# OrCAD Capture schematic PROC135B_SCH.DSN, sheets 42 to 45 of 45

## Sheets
42 42. OSCILLATOR: size C; title: SOC RESETs AND IOs, AND EXTERNAL LVCMOS CLOCK (OSCILLATOR)
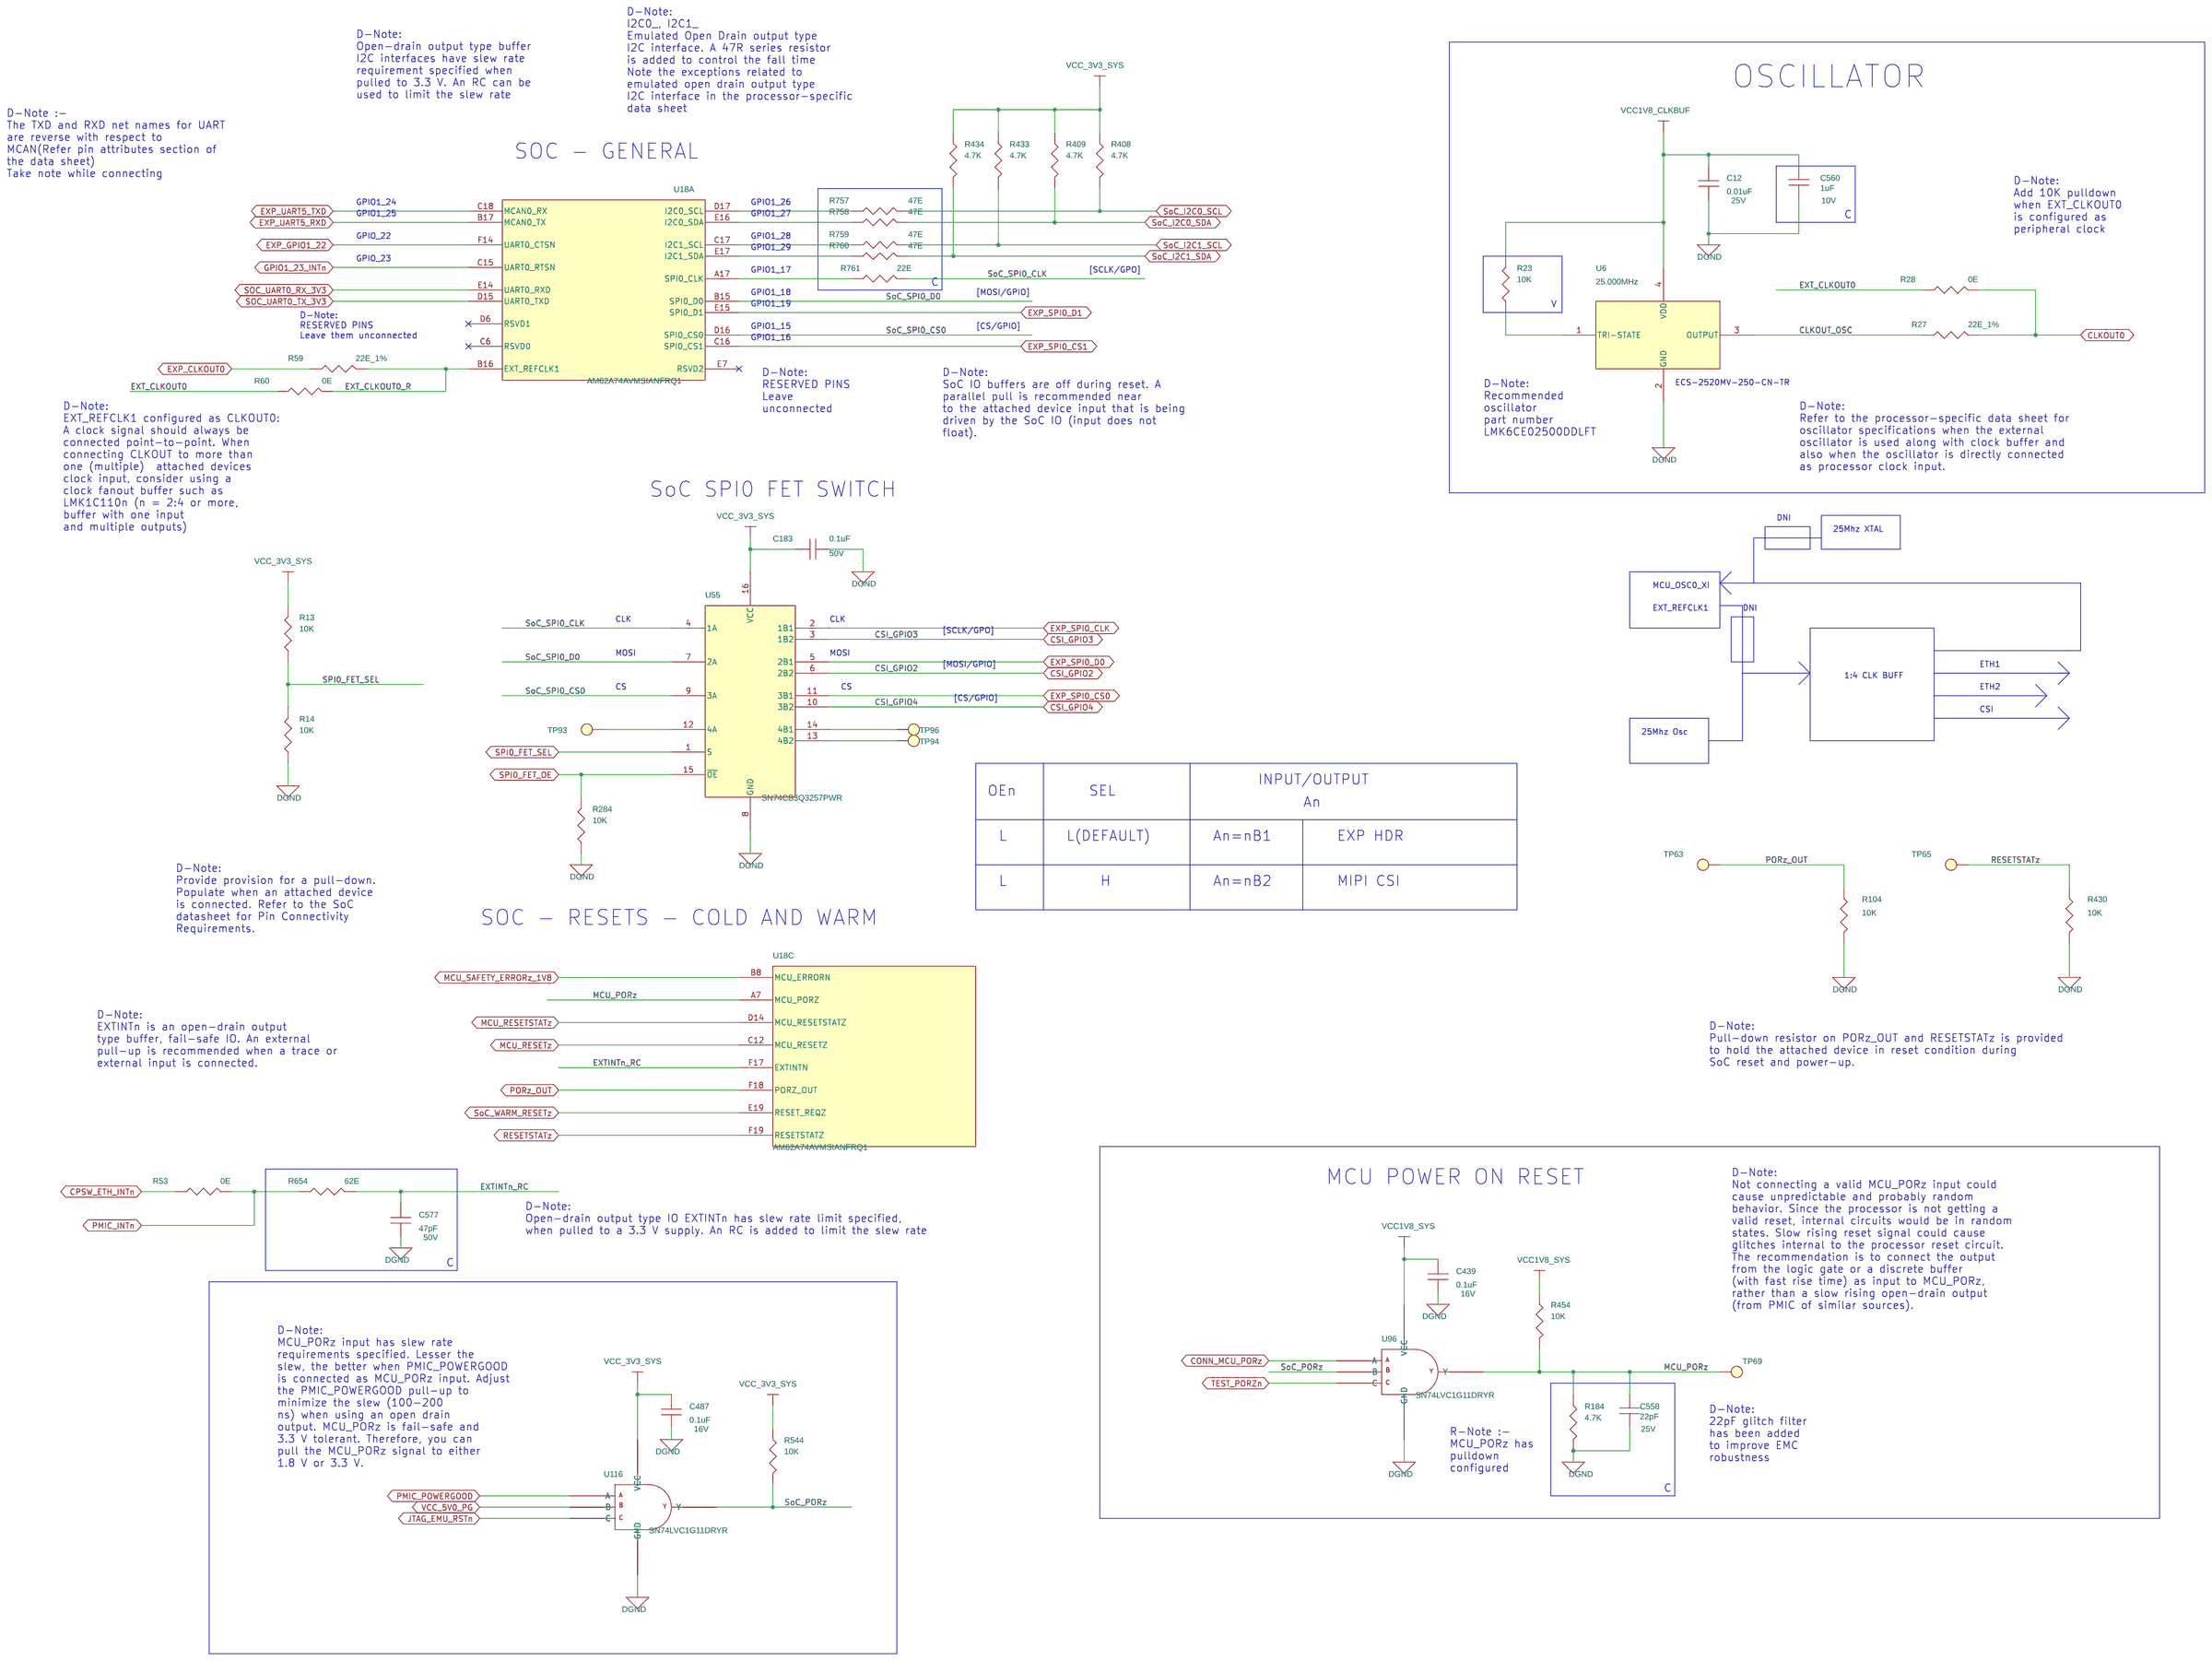
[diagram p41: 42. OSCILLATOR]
43 43. RESET: size C; title: SOC RESETS - COLD AND WARM
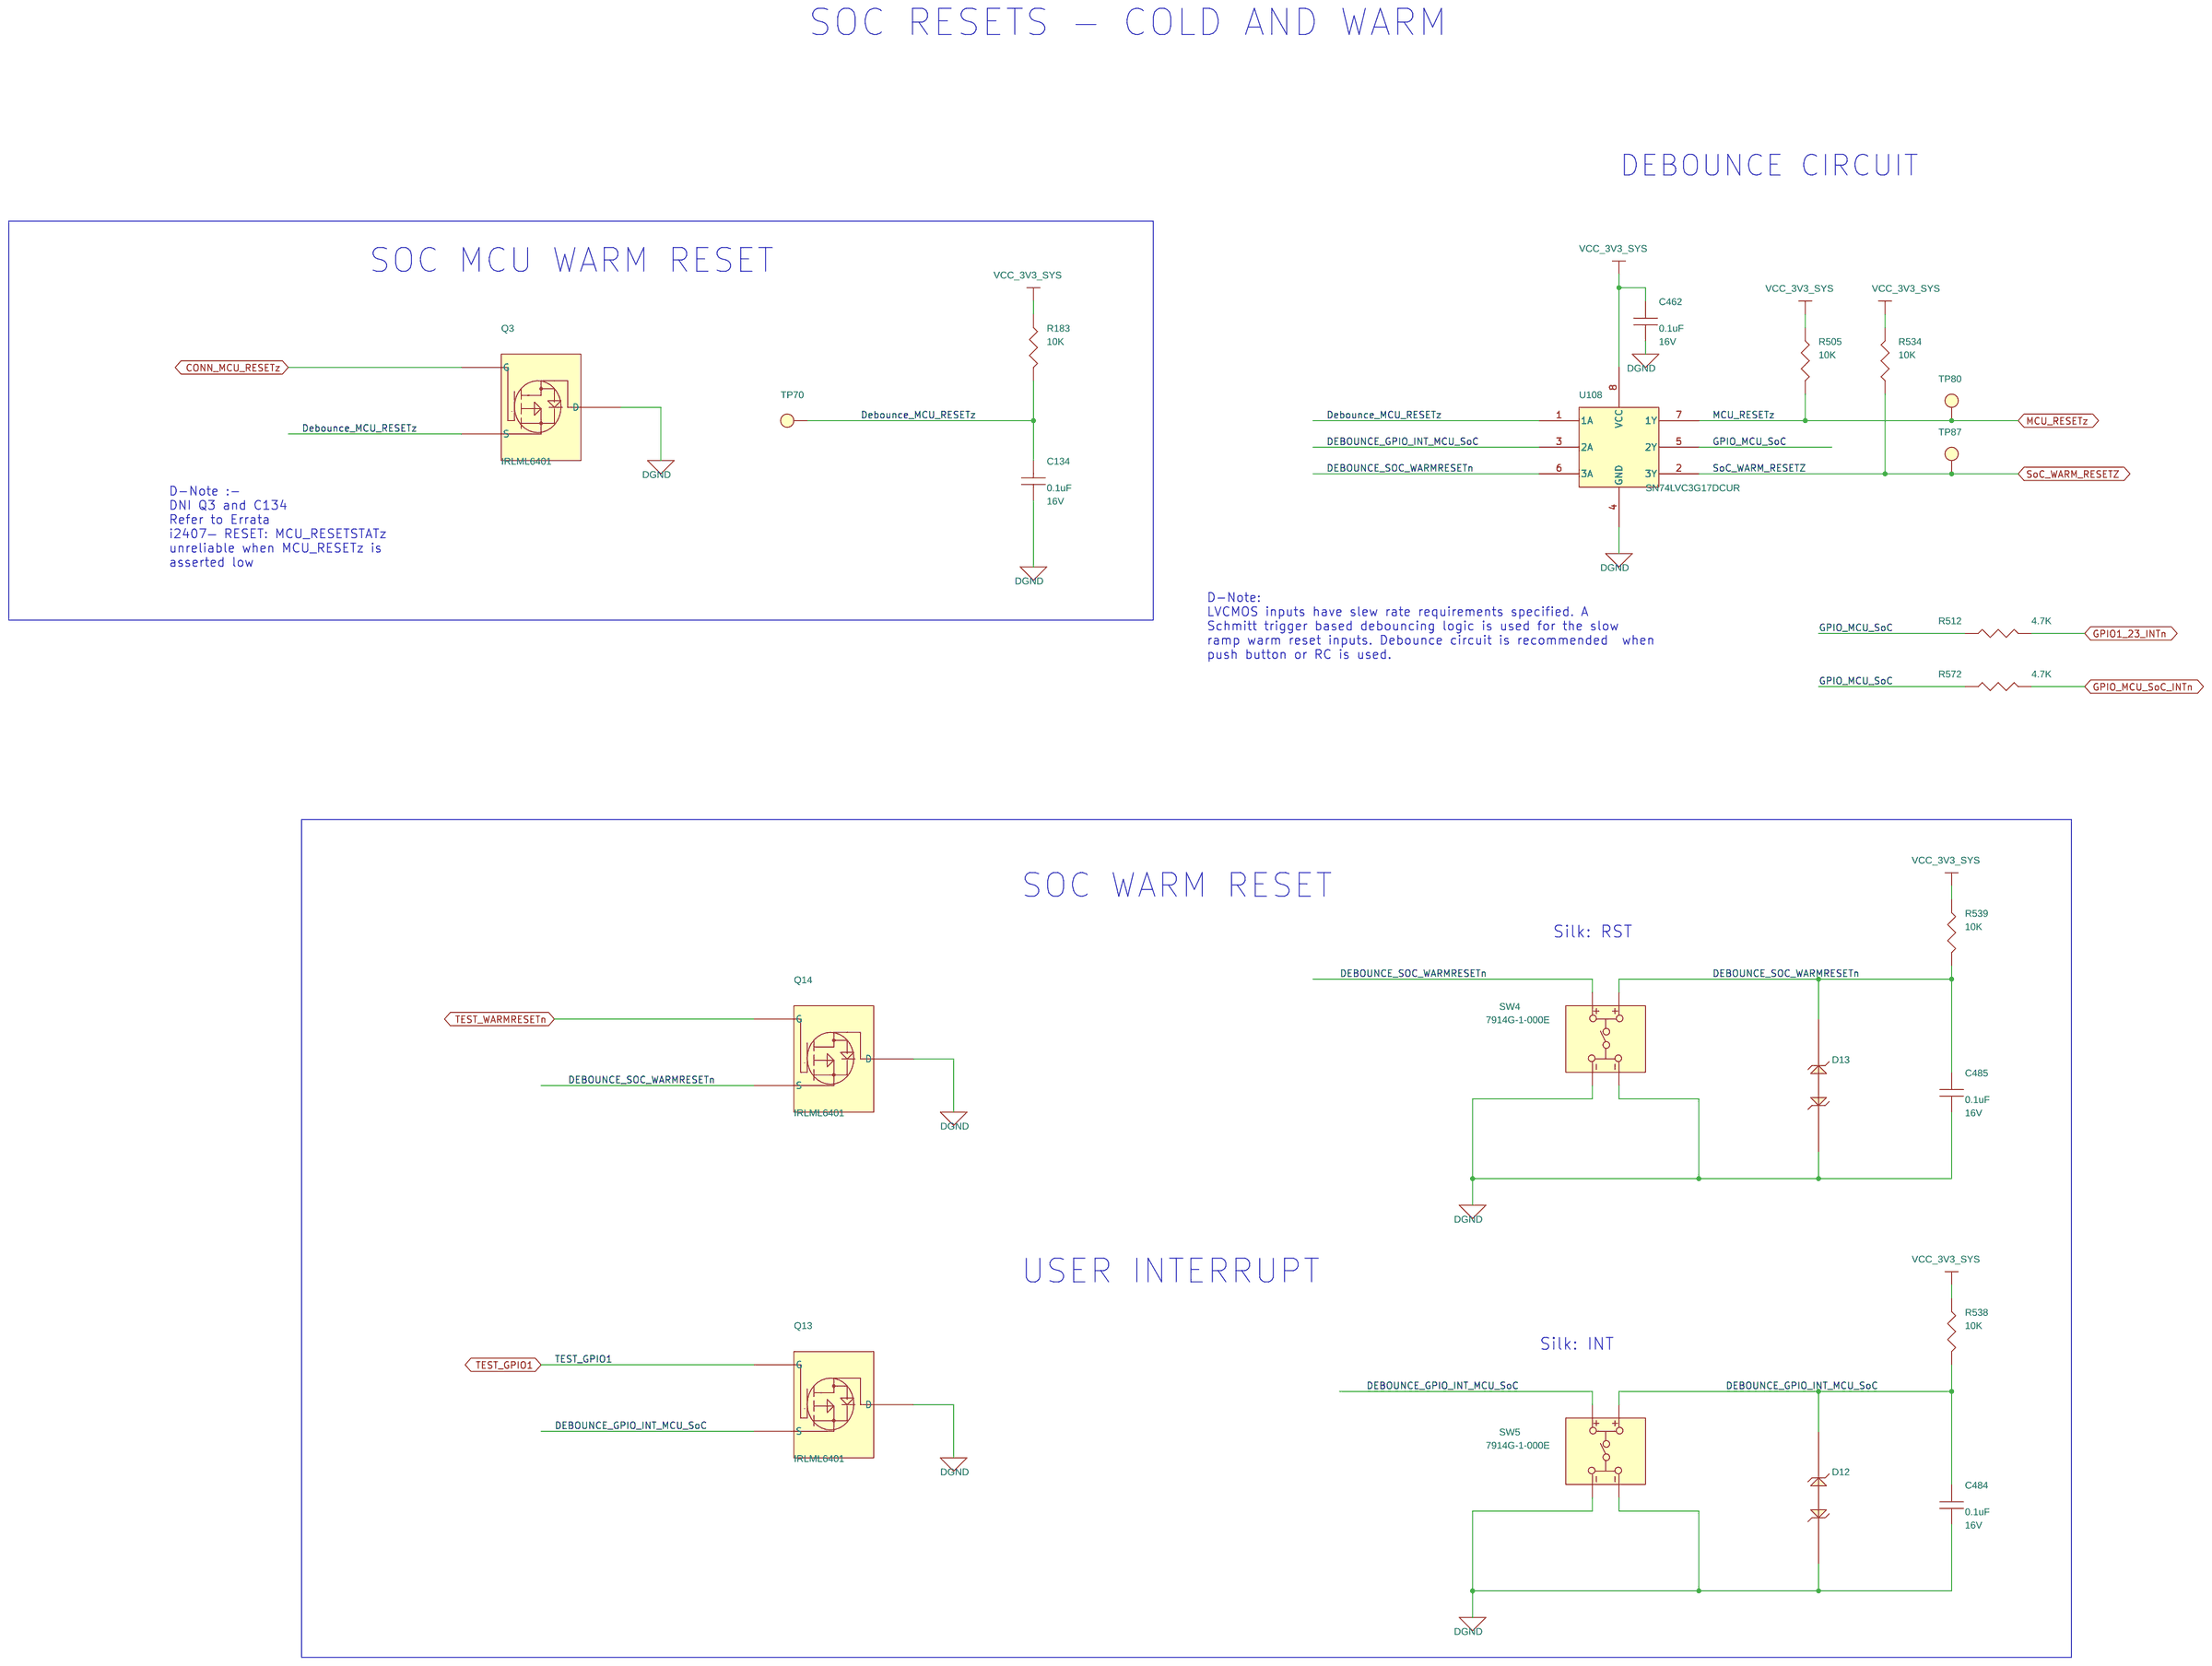
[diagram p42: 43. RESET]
44 44. CAN_FD_WKUP_SW: size C; title: EXTERNAL SWITCH FOR CAN FD WKUP
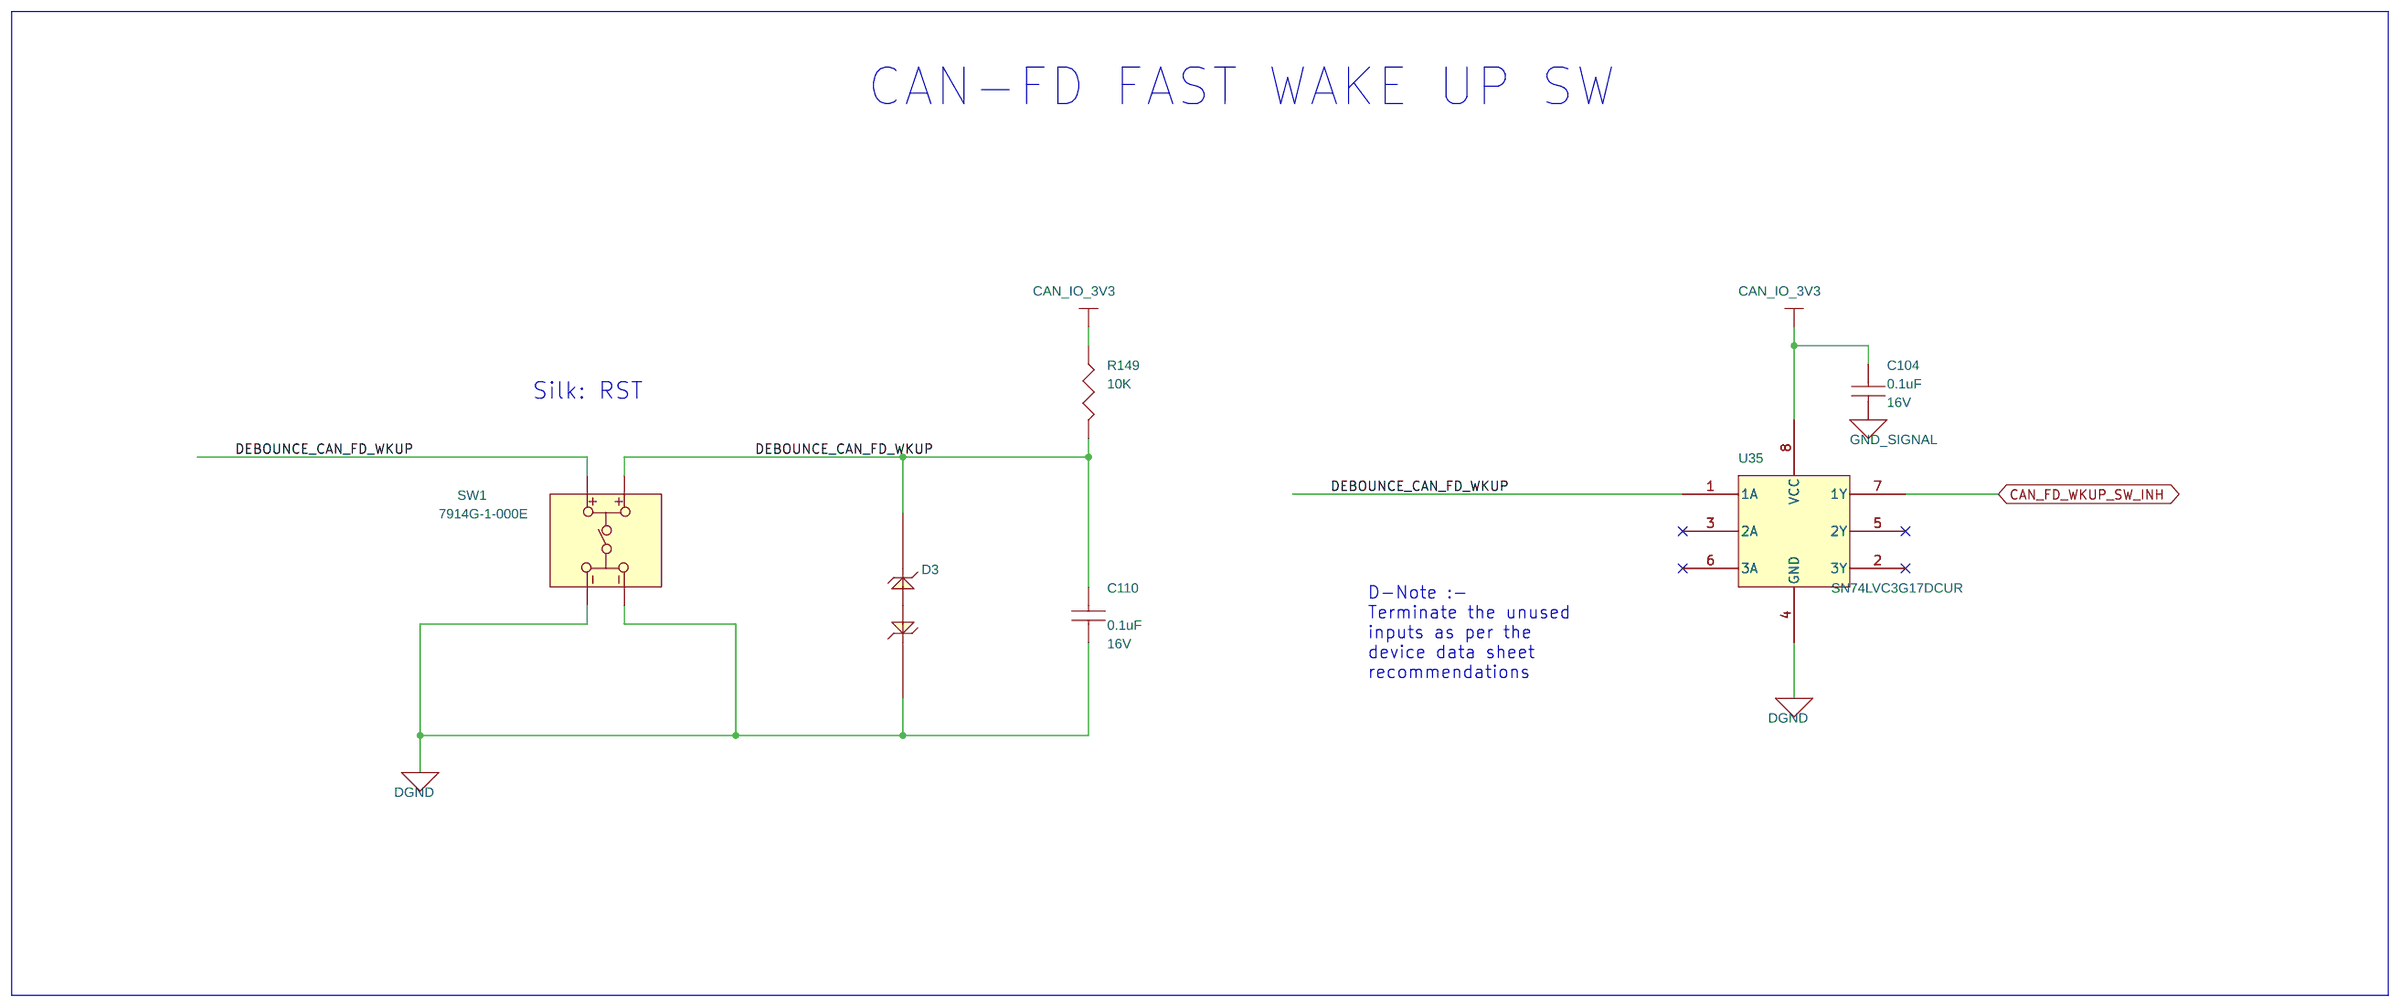
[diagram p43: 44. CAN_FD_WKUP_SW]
45 45. ACCESSORIES: title: ASSEMBLY NOTES AND MOUNTING HARDWARE
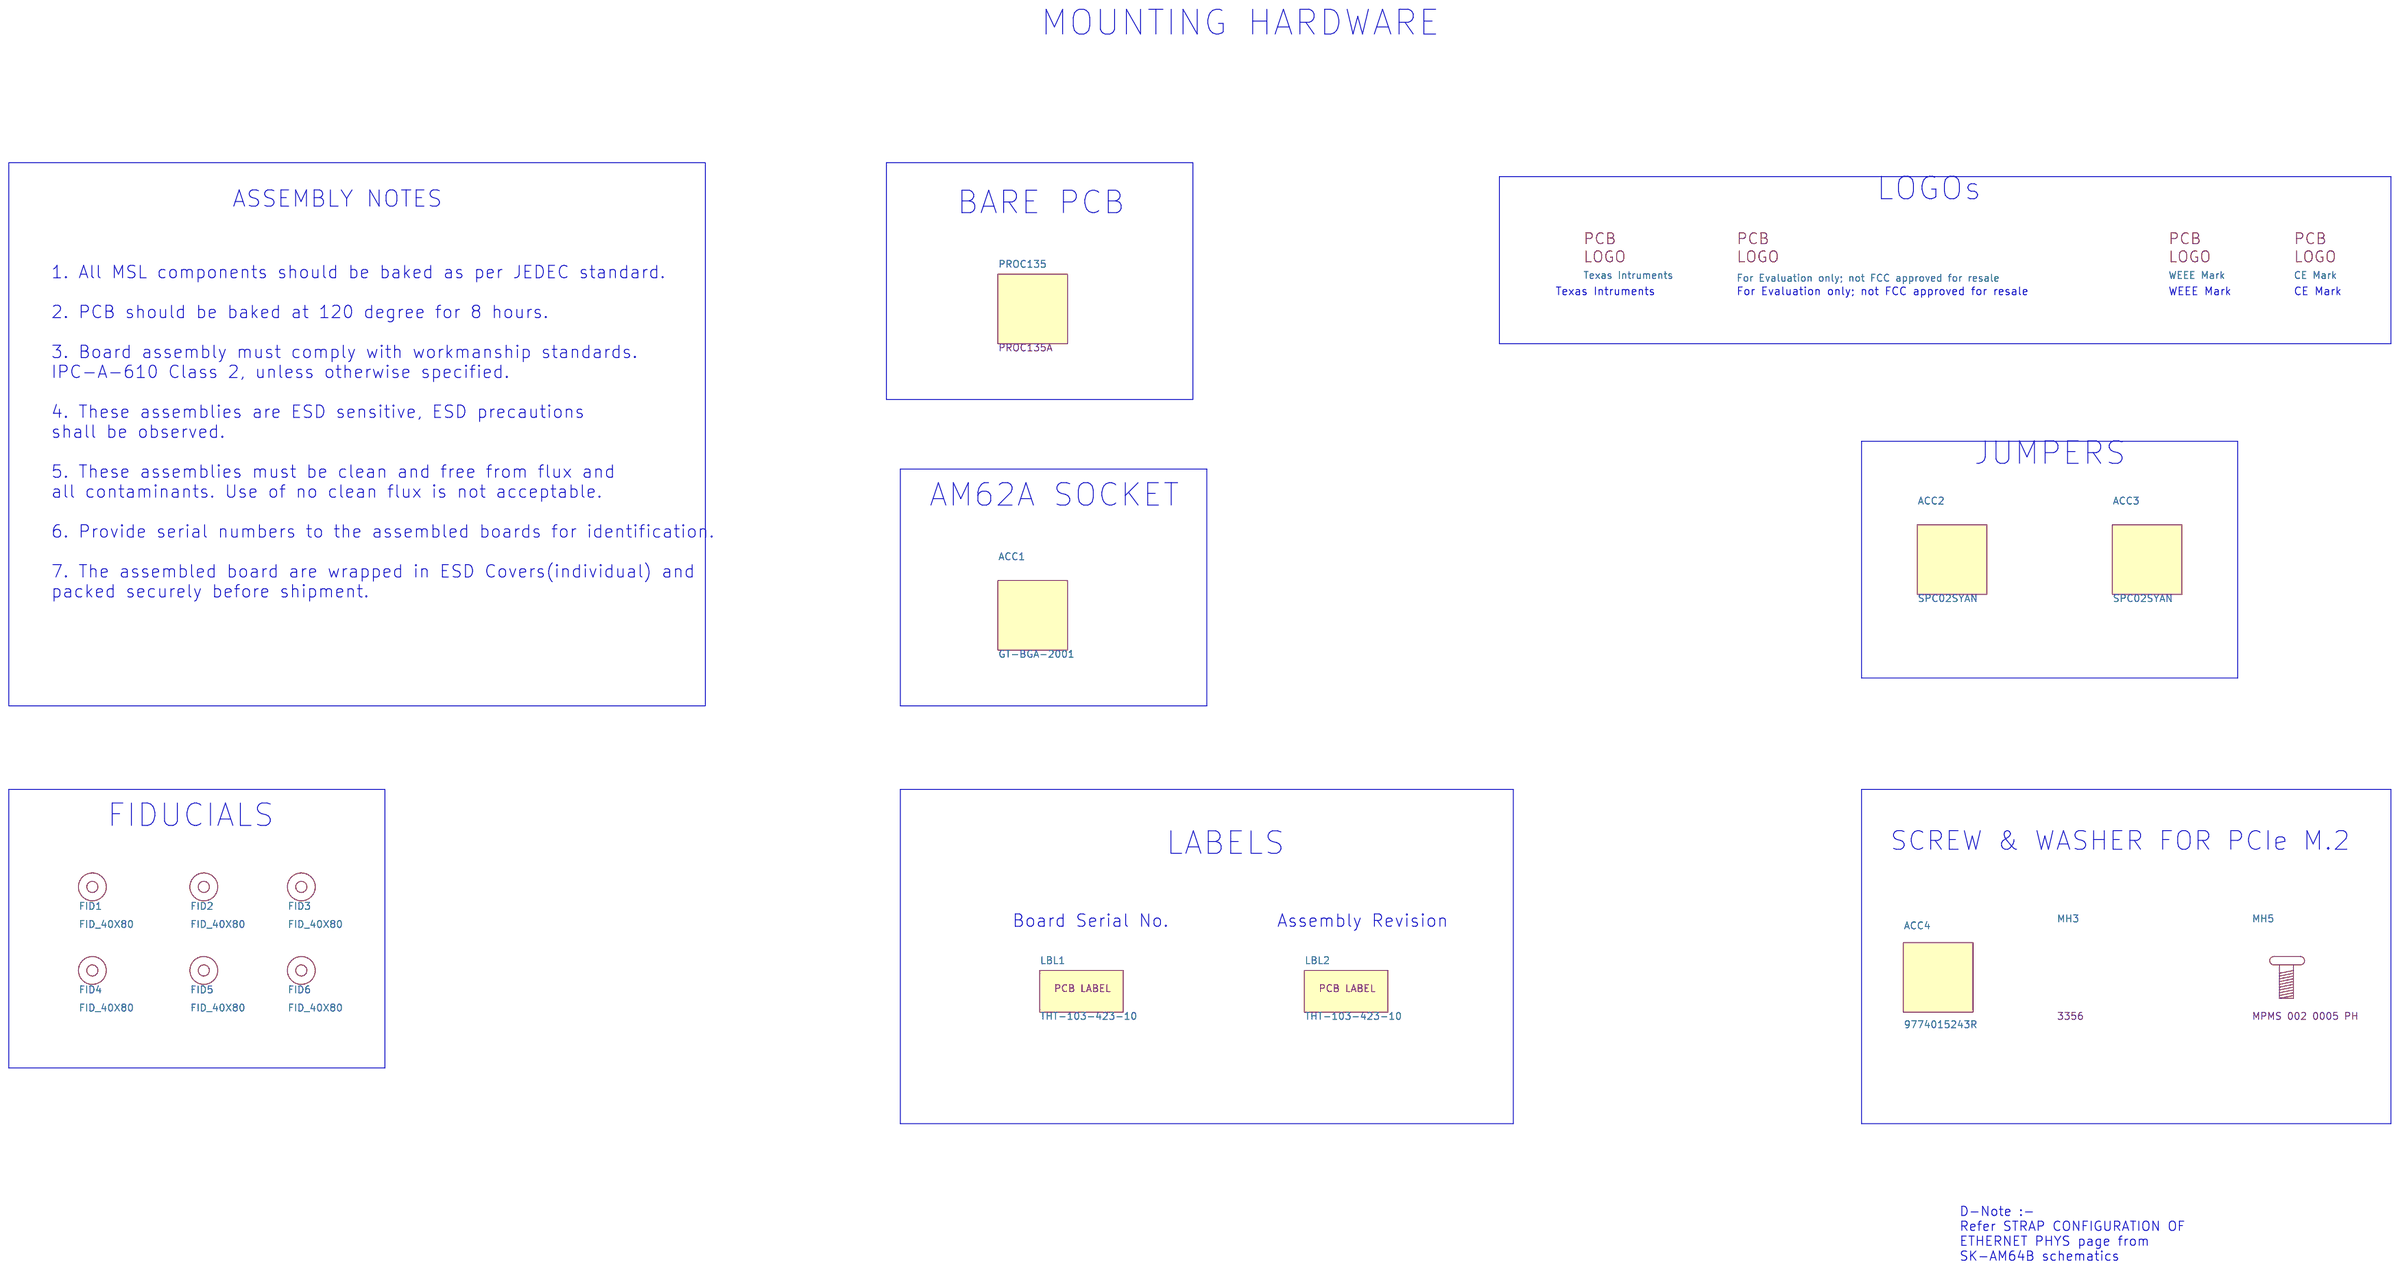
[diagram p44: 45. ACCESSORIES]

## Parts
sheet 34. MCU HEADER
U18  AM62A74AVMSIANFRQ1  [FBGA484_31-49_710X710_2-7]  (sections A,B,C,D,E,F,G,H,I,J,K,L,M,N,O,P,Q)
sheet 42. OSCILLATOR
C12  0.01uF  [CAP0201_0-5]
C183  0.1uF  [CAP0402_0-75]
C439  0.1uF  [CAP0201_0-5]
C487  0.1uF  [CAP0201_0-5]
C558  22pF  [CAP0402_0-75]
C560  1uF  [CAP0201_0-5]
C577  47pF  [CAP0201_0-5]
R13  10K  [RES0201_0-5]
R14  10K  [RES0201_0-5]
R23  10K  [RES0201_0-5]
R27  22E_1%  [RES0201_0-5]
R28  0E  [RES0201_0-5]
R53  0E  [RES0201_0-5]
R59  22E_1%  [RES0201_0-5]
R60  0E  [RES0201_0-5]
R104  10K  [RES0201_0-5]
R184  4.7K  [RES0201_0-5]
R284  10K  [RES0201_0-5]
R408  4.7K  [RES0201_0-5]
R409  4.7K  [RES0201_0-5]
R430  10K  [RES0201_0-5]
R433  4.7K  [RES0201_0-5]
R434  4.7K  [RES0201_0-5]
R454  10K  [RES0201_0-5]
R544  10K  [RES0201_0-5]
R654  62E  [RES0402_0-5]
R757  47E  [RES0201_0-5]
R758  47E  [RES0201_0-5]
R759  47E  [RES0201_0-5]
R760  47E  [RES0201_0-5]
R761  22E  [RES0201_0-5]
TP63  TP20_SMD  [TP20_SMD]
TP65  TP20_SMD  [TP20_SMD]
TP69  TP20_SMD  [TP20_SMD]
TP93  TP20_SMD  [TP20_SMD]
TP94  TP20_SMD  [TP20_SMD]
TP96  TP20_SMD  [TP20_SMD]
U6  25.000MHz  [OSC4_ECS-2520MV_100X80_SMD_0-9]
U55  SN74CB3Q3257PWR  [TSSOP16_25-59_205X180]
U96  SN74LVC1G11DRYR  [SON6_SN74LVC2G17_40X60_0-6]
U116  SN74LVC1G11DRYR  [SON6_SN74LVC2G17_40X60_0-6]
sheet 43. RESET
C134  0.1uF  [CAP0201_0-5]
C462  0.1uF  [CAP0201_0-5]
C484  0.1uF  [CAP0201_0-5]
C485  0.1uF  [CAP0201_0-5]
D12  TPD1E10B06DPYR  [DIO_DFN0402_0-5]
D13  TPD1E10B06DPYR  [DIO_DFN0402_0-5]
Q3  IRLML6401  [TO_SOT23-123]
Q13  IRLML6401  [TO_SOT23-123]
Q14  IRLML6401  [TO_SOT23-123]
R183  10K  [RES0201_0-5]
R505  10K  [RES0201_0-5]
R512  4.7K  [RES0201_0-5]
R534  10K  [RES0201_0-5]
R538  10K  [RES0201_0-5]
R539  10K  [RES0201_0-5]
R572  4.7K  [RES0201_0-5]
SW4  7914G-1-000E  [SW4_100X216_200X200_SMD_4-2]
SW5  7914G-1-000E  [SW4_100X216_200X200_SMD_4-2]
TP70  TP20_SMD  [TP20_SMD]
TP80  TP20_SMD  [TP20_SMD]
TP87  TP20_SMD  [TP20_SMD]
U108  SN74LVC3G17DCUR  [VSSOP8_19-68_85X95_0-9]
sheet 44. CAN_FD_WKUP_SW
C104  0.1uF  [CAP0201_0-5]
C110  0.1uF  [CAP0201_0-5]
D3  TPD1E10B06DPYR  [DIO_DFN0402_0-5]
R149  10K  [RES0201_0-5]
SW1  7914G-1-000E  [SW4_100X216_200X200_SMD_4-2]
U35  SN74LVC3G17DCUR  [VSSOP8_19-68_85X95_0-9]
sheet 45. ACCESSORIES
ACC1  GT-BGA-2001  [BGASKT484_GT-BGA-2001_910X910_10-7]
ACC2  SPC02SYAN  [NA]
ACC3  SPC02SYAN  [NA]
ACC4  9774015243R  [NA]
FID1  FID_40X80  [FID_40X80]
FID2  FID_40X80  [FID_40X80]
FID3  FID_40X80  [FID_40X80]
FID4  FID_40X80  [FID_40X80]
FID5  FID_40X80  [FID_40X80]
FID6  FID_40X80  [FID_40X80]
LBL1  THT-103-423-10  [NA]
LBL2  THT-103-423-10  [NA]
LOGO1  Texas Intruments  [TI_Stacked_Overlay_Small]
LOGO2  For Evaluation only; not FCC approved for resale  [FCC_disclaimer]
LOGO3  WEEE Mark  [TI_Stacked_Overlay_Small]
LOGO4  CE Mark  [TI_Stacked_Overlay_Small]
MH3  FLAT WASHER_M2  [NA]
MH5  PAN HEAD_M2 X 5  [NA]
PCB1  PROC135

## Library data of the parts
U18 = AM62A-EVM_SOC_FCBGA484: IC AM62A SK EVM SoC MICROPROCESSOR FCBGA484; Chkd/date: PRADEEP/120225; Crtd /date: SHANKARI/120225; Custom_Duty: 15%; Customs_HS_Code: 85369090; Distributor_name: NA; Distributor_part_number: NA; Footprint Path: Y:\MIS_DATABASE\Library\ALTIUM_TOOL\PCB_FOOTPRINTS\Altium_Footprint_Lib.PcbLib; Height: 2.65MM; Library Path: Y:\MIS_DATABASE\Library\ALTIUM_TOOL\SCHEMATICS_PARTS\MS_MICROPROCESSOR_Library.schlib; Library Ref: AM62A-EVM_SoC_FCBGA484; Mfr_name: TEXAS INSTRUMENTS; Mistral Part No: 141225020003-R; Package: FCBGA484; Part_type: ICS\DIGITAL\MICROPROCESSOR; Project: AM62A_SK_EVM; RoHS: NA; Temperature: NA; Tolerance: NA; Voltage: NA; Wattage: NA; Weight: NA; Datasheet: Y:\MIS_DATABASE\DATASHEETS\ICS\DIGITAL\MICROCONTROLLER\AM62A_SK_EVM.PDF
C12 = CAP: CAP CERAMIC 0.01uF 25V 10% X5R AUTO 0201; Chkd/date: MANIRAJA/311221; Crtd /date: ALVY/301221; Custom_Duty: 15%; Customs_HS_Code: 85322990; Distributor_name: MOUSER; Distributor_part_number: 81-GRT033R61E103KE1D; Footprint Path: Y:\MIS_DATABASE\Library\ALTIUM_TOOL\PCB_FOOTPRINTS\Altium_Footprint_Lib.PcbLib; Height: 0.33MM; Library Path: Y:\MIS_DATABASE\Library\ALTIUM_TOOL\SCHEMATICS_PARTS\MS_DISCRETE_Library.schlib; Mfr_name: MURATA; Mfr_part_number: GRT033R61E103KE01D; Mistral Part No: 120021120019-R; Package: 0201; Part_type: CAPACITORS\CERAMIC; Project: AM62Q_SKEVM_BRD; RoHS: RoHS; Temperature: -55°C+85°C; Tolerance: 10%; Voltage: 25V; Wattage: NA; Weight: 0.33mg; Datasheet: Y:\MIS_DATABASE\DATASHEETS\CAPACITORS\GRT033R61E103KE01.PDF
C183 = CAP: CAP CERAMIC 0.1uF 50V 10% X7R AUTO 0402; Alt_Mfr_name: YAGEO AMERICA; Alt_Mfr_part_number: CC0402KRX5R8BB104; Chkd/date: MANIRAJA/250221; Crtd /date: ALVY/240221; Custom_Duty: 15%; Customs_HS_Code: 85322990; Distributor_name: MOUSER; Distributor_part_number: 81-GRT155R71H104KE1D; Footprint Path: Y:\MIS_DATABASE\Library\ALTIUM_TOOL\PCB_FOOTPRINTS\Altium_Footprint_Lib.PcbLib; Height: 0.55MM; Library Path: Y:\MIS_DATABASE\Library\ALTIUM_TOOL\SCHEMATICS_PARTS\MS_DISCRETE_Library.schlib; Mfr_name: MURATA; Mfr_part_number: GRT155R71H104KE01D; Mistral Part No: 120019030005-R; Package: 0402; Part_type: CAPACITORS\CERAMIC; Project: TI_DRA821 SK EVM BRD; RoHS: RoHS; Temperature: -55°C+125°C; Tolerance: 10%; Voltage: 50V; Wattage: NA; Weight: NA; Datasheet: Y:\MIS_DATABASE\DATASHEETS\CAPACITORS\GRT155R71H104KE01.PDF
C104 C110 C134 C439 C462 C484 C485 C487 = CAP: CAP CERAMIC 0.1uF 16V 10% X5R 0201; Alt_Mfr_name: YAGEO AMERICA; Alt_Mfr_part_number: CC0402KRX5R8BB104; Chkd/date: PRADEEP/130623; Crtd /date: PRADEEP/130623; Custom_Duty: 15%; Customs_HS_Code: 85322990; Distributor_name: NA; Distributor_part_number: NA; Footprint Path: Y:\MIS_DATABASE\Library\ALTIUM_TOOL\PCB_FOOTPRINTS\Altium_Footprint_Lib.PcbLib; Height: 0.33MM; Library Path: Y:\MIS_DATABASE\Library\ALTIUM_TOOL\SCHEMATICS_PARTS\MS_DISCRETE_Library.schlib; Mfr_name: MURATA; Mfr_part_number: GRT033R61C104KE01; Mistral Part No: 120022060019-R; Package: 0201; Part_type: CAPACITORS\CERAMIC; Project: AM62P_SK; RoHS: RoHS; Temperature: -55°C+85°C; Tolerance: 10%; Voltage: 16V; Wattage: NA; Weight: 0.33mg; Datasheet: Y:\MIS_DATABASE\DATASHEETS\CAPACITORS\GRT033R61C104KE01XX.PDF
C558 = CAP: CAP CERAMIC 22pF 25V 5% C0G(NP0) 0402; Chkd/date: PRADEEP/230824; Crtd /date: SHANKARI/230824; Custom_Duty: 15%; Customs_HS_Code: 85322990; Distributor_name: DIGIKEY; Distributor_part_number: 490-GRT1555C1E220JA02JCT-ND; Footprint Path: Y:\MIS_DATABASE\Library\ALTIUM_TOOL\PCB_FOOTPRINTS\Altium_Footprint_Lib.PcbLib; Height: 0.55MM; Library Path: Y:\MIS_DATABASE\Library\ALTIUM_TOOL\SCHEMATICS_PARTS\MS_DISCRETE_Library.schlib; Mfr_name: MURATA; Mfr_part_number: GRT1555C1E220JA02J; Mistral Part No: 120024080046-R; Package: 0402; Part_type: CAPACITORS\CERAMIC; Project: QCS2290_BASED_QIOT_PLATFORM; RoHS: RoHS; Temperature: -55°C+125°C; Tolerance: 5%; Voltage: 25V; Wattage: NA; Weight: NA; Datasheet: Y:\MIS_DATABASE\DATASHEETS\CAPACITORS\GRT1555C1E220JA02J.PDF
C560 = CAP: CAP CERAMIC 1uF 10V 20% X5R 0201; Chkd/date: NAVEED/070415; Crtd /date: VASANTHA/230314; Custom_Duty: 15%; Customs_HS_Code: 85322990; Distributor_name: DIGIKEY; Distributor_part_number: 1276-1324-1-ND; Footprint Path: Y:\MIS_DATABASE\Library\ALTIUM_TOOL\PCB_FOOTPRINTS\Altium_Footprint_Lib.PcbLib; Height: 0.35MM; Library Path: Y:\MIS_DATABASE\Library\ALTIUM_TOOL\SCHEMATICS_PARTS\MS_DISCRETE_Library.schlib; Mfr_name: SAMSUNG; Mfr_part_number: CL03A105MP3NSNC; Mistral Part No: 120015030003-R; Package: 0201; Part_type: CAPACITORS\CERAMIC; Project: DUET BOARDS; RoHS: RoHS; Temperature: -55°C+85°C; Tolerance: 20%; Voltage: 10V; Wattage: NA; Weight: 0.17mg; Datasheet: Y:\MIS_DATABASE\DATASHEETS\CAPACITORS\CL03A105MP3NSNC.PDF
C577 = CAP: CAP CERAMIC 47pF 50V 5% C0G(NP0) AUTO 0201; Chkd/date: MANIRAJA/311221; Crtd /date: ALVY/301221; Custom_Duty: 15%; Customs_HS_Code: 85322990; Distributor_name: MOUSER; Distributor_part_number: 81-GRT0335C1H470JA2D; Footprint Path: Y:\MIS_DATABASE\Library\ALTIUM_TOOL\PCB_FOOTPRINTS\Altium_Footprint_Lib.PcbLib; Height: 0.33MM; Library Path: Y:\MIS_DATABASE\Library\ALTIUM_TOOL\SCHEMATICS_PARTS\MS_DISCRETE_Library.schlib; Mfr_name: MURATA; Mfr_part_number: GRT0335C1H470JA02D; Mistral Part No: 120021120018-R; Package: 0201; Part_type: CAPACITORS\CERAMIC; Project: AM62Q_SKEVM_BRD; RoHS: RoHS; Temperature: -55°C+125°C; Tolerance: 5%; Voltage: 50V; Wattage: NA; Weight: 0.33mg; Datasheet: Y:\MIS_DATABASE\DATASHEETS\CAPACITORS\GRT0335C1H470JA02.PDF
R13 R14 R23 R104 R149 R183 R284 R430 R454 R505 R534 R538 R539 R544 = RESISTOR: RES 10K 1/20W 5% 0201; Chkd/date: MANIRAJA/050517; Crtd /date: MANIRAJA/050517; Custom_Duty: 15%; Customs_HS_Code: 85332119; Distributor_name: DIGIKEY; Distributor_part_number: 311-10KNCT-ND; Footprint Path: Y:\MIS_DATABASE\Library\ALTIUM_TOOL\PCB_FOOTPRINTS\Altium_Footprint_Lib.PcbLib; Height: 0.26MM; Library Path: Y:\MIS_DATABASE\Library\ALTIUM_TOOL\SCHEMATICS_PARTS\MS_DISCRETE_Library.schlib; Mfr_name: YAGEO AMERICA; Mfr_part_number: RC0201JR-0710KL; Mistral Part No: 110010070051-R; Package: 0201; Part_type: RESISTORS\FIXED; Project: GOLDEN-I LITE; RoHS: RoHS; Temperature: -55°C+125°C; Tolerance: 5%; Voltage: NA; Wattage: 1/20W; Weight: 0.17mg; Datasheet: Y:\MIS_DATABASE\DATASHEETS\RESISTORS\RCXXXXL-SER_MAR18.PDF
R27 R59 = RESISTOR: RES 22E 1/20W 1% 0201; Chkd/date: MANIRAJA/080319; Crtd /date: ALVY/080319; Custom_Duty: 15%; Customs_HS_Code: 85332119; Distributor_name: DIGIKEY; Distributor_part_number: YAG2518CT-ND; Footprint Path: Y:\MIS_DATABASE\Library\ALTIUM_TOOL\PCB_FOOTPRINTS\Altium_Footprint_Lib.PcbLib; Height: 0.26MM; Library Path: Y:\MIS_DATABASE\Library\ALTIUM_TOOL\SCHEMATICS_PARTS\MS_DISCRETE_Library.schlib; Mfr_name: YAGEO AMERICA; Mfr_part_number: RC0201FR-0722RL; Mistral Part No: 110009030522-R; Package: 0201; Part_type: RESISTORS\FIXED; Project: AM654x_SOM; RoHS: RoHS; Temperature: -55°C+125°C; Tolerance: 1%; Voltage: NA; Wattage: 1/20W; Weight: 0.17mg; Datasheet: Y:\MIS_DATABASE\DATASHEETS\RESISTORS\RCXXXXL-SER_MAR18.PDF
R28 R53 R60 = RESISTOR: RES 0E 1/20W 5% 0201; Chkd/date: NAVEED/301214; Crtd /date: MUDDU/120710; Custom_Duty: 15%; Customs_HS_Code: 85332119; Distributor_name: DIGIKEY; Distributor_part_number: 311-0.0NCT-ND; Footprint Path: Y:\MIS_DATABASE\Library\ALTIUM_TOOL\PCB_FOOTPRINTS\Altium_Footprint_Lib.PcbLib; Height: 0.26MM; Library Path: Y:\MIS_DATABASE\Library\ALTIUM_TOOL\SCHEMATICS_PARTS\MS_DISCRETE_Library.schlib; Mfr_name: YAGEO AMERICA; Mfr_part_number: RC0201JR-070RL; Mistral Part No: 110010070067-R; Package: 0201; Part_type: RESISTORS\FIXED; Project: PB_BUGBASE; RoHS: RoHS; Temperature: -55°C+125°C; Tolerance: 5%; Voltage: NA; Wattage: 1/20W; Weight: 0.17mg; Datasheet: Y:\MIS_DATABASE\DATASHEETS\RESISTORS\RCXXXXL-SER_MAR18.PDF
R184 R408 R409 R433 R434 = RESISTOR: RES 4.7K 1/20W 5% 0201; Chkd/date: MANIRAJA/200921; Crtd /date: ALVY/200921; Custom_Duty: 15%; Customs_HS_Code: 85332119; Distributor_name: DIGIKEY; Distributor_part_number: 311-4.7KNCT-ND; Footprint Path: Y:\MIS_DATABASE\Library\ALTIUM_TOOL\PCB_FOOTPRINTS\Altium_Footprint_Lib.PcbLib; Height: 0.26MM; Library Path: Y:\MIS_DATABASE\Library\ALTIUM_TOOL\SCHEMATICS_PARTS\MS_DISCRETE_Library.schlib; Mfr_name: YAGEO AMERICA; Mfr_part_number: RC0201JR-074K7L; Mistral Part No: 110021090007-R; Package: 0201; Part_type: RESISTORS\FIXED; Project: TI_AM62x SKEVM_BRD; RoHS: RoHS; Temperature: -55°C+125°C; Tolerance: 5%; Voltage: NA; Wattage: 1/20W; Weight: 0.17mg; Datasheet: Y:\MIS_DATABASE\DATASHEETS\RESISTORS\RCXXXXL-SER_MAR18.PDF
R654 = RESISTOR: RES 62E 1/10W 5% 0402; Chkd/date: SHREESHAIL/070606; Crtd /date: GEETHA/070606; Custom_Duty: 15%; Customs_HS_Code: 85332119; Distributor_name: DIGIKEY; Distributor_part_number: P62JCT-ND; Footprint Path: Y:\MIS_DATABASE\Library\ALTIUM_TOOL\PCB_FOOTPRINTS\Altium_Footprint_Lib.PcbLib; Height: 0.40MM; Library Path: Y:\MIS_DATABASE\Library\ALTIUM_TOOL\SCHEMATICS_PARTS\MS_DISCRETE_Library.schlib; Mfr_name: PANASONIC-ECG; Mfr_part_number: ERJ-2GEJ620X; Mistral Part No: 110009031047-R; Package: 0402; Part_type: RESISTORS\FIXED; Project: VOCERA; RoHS: RoHS; Temperature: -55°C+155°C; Tolerance: 5%; Voltage: NA; Wattage: 1/10W; Weight: 0.8mg; Datasheet: Y:\MIS_DATABASE\DATASHEETS\RESISTORS\PAN-ERJSER_NOV17.PDF
R757-R760 = RESISTOR: RES 47E 1/20W 5% 0201; Chkd/date: MAZHAR/140709; Crtd /date: MAZHAR/260907; Custom_Duty: 15%; Customs_HS_Code: 85332119; Distributor_name: DIGIKEY; Distributor_part_number: P47AGCT-ND; Footprint Path: Y:\MIS_DATABASE\Library\ALTIUM_TOOL\PCB_FOOTPRINTS\Altium_Footprint_Lib.PcbLib; Height: 0.26MM; Library Path: Y:\MIS_DATABASE\Library\ALTIUM_TOOL\SCHEMATICS_PARTS\MS_DISCRETE_Library.schlib; Mfr_name: PANASONIC-ECG; Mfr_part_number: ERJ-1GEJ470C; Mistral Part No: 110009030875-R; Package: 0201; Part_type: RESISTORS\FIXED; Project: SMART VIEW_NVR; RoHS: RoHS; Temperature: -55°C+125°C; Tolerance: 5%; Voltage: NA; Wattage: 1/20W; Weight: 0.15mg; Datasheet: Y:\MIS_DATABASE\DATASHEETS\RESISTORS\PAN-ERJXGE-FEB06.PDF
R761 = RESISTOR: RES 22E 1/20W 5% 0201; Chkd/date: PRADEEP/220424; Crtd /date: SHANKARI/220424; Custom_Duty: 15%; Customs_HS_Code: 85332119; Distributor_name: DIGIKEY; Distributor_part_number: 311-22NCT-ND; Footprint Path: Y:\MIS_DATABASE\Library\ALTIUM_TOOL\PCB_FOOTPRINTS\Altium_Footprint_Lib.PcbLib; Height: 0.26MM; Library Path: Y:\MIS_DATABASE\Library\ALTIUM_TOOL\SCHEMATICS_PARTS\MS_DISCRETE_Library.schlib; Manufacturer: YAGEO; Mfr_name: YAGEO; Mfr_part_number: RC0201JR-0722RL; Mistral Part No: 110024040012-R; Package: 0201; Part_type: RESISTORS\FIXED; Project: J7AEN_SKEVM; RoHS: RoHS; Temperature: -55°C+125°C; Tolerance: 5%; Voltage: NA; Wattage: 1/20W; Weight: NA; Datasheet: Y:\MIS_DATABASE\DATASHEETS\RESISTORS\RC0201JR-0722RL.PDF
TP63 TP65 TP69 TP70 TP80 TP87 TP93 TP94 TP96 = TESTPOINT: TESTPOINT CIR 20 SMD; Chkd/date: SHREESHAIL/171006; Crtd /date: MAZHAR/171006; Custom_Duty: NA; Customs_HS_Code: NA; Distributor_name: NA; Distributor_part_number: NA; Footprint Path: Y:\MIS_DATABASE\Library\ALTIUM_TOOL\PCB_FOOTPRINTS\Altium_Footprint_Lib.PcbLib; Height: NA; Library Path: Y:\MIS_DATABASE\Library\ALTIUM_TOOL\SCHEMATICS_PARTS\MS_DISCRETE_Library.schlib; MECHANICAL 3D STEP FILE: NA; Mfr_name: LOCAL; Mistral Part No: NA; Package: SMD; Project: BT MODULE_CSRBC04; RoHS: NA; Temperature: NA; Tolerance: NA; Voltage: NA; Wattage: NA; Weight: NA; Datasheet: NA
U6 = OSC4_ASFL3: OSC 25.000MHz CMOS SMD; Chkd/date: MANIRAJA/181120; Crtd /date: ALVY/181120; Custom_Duty: 24%; Customs_HS_Code: 85437099; Distributor_name: DIGIKEY; Distributor_part_number: XC2752CT-ND; Footprint Path: Y:\MIS_DATABASE\Library\ALTIUM_TOOL\PCB_FOOTPRINTS\Altium_Footprint_Lib.PcbLib; Height: 0.90MM; Library Path: Y:\MIS_DATABASE\Library\ALTIUM_TOOL\SCHEMATICS_PARTS\MS_DISCRETE_Library.schlib; Mfr_name: ECS INC; Mfr_part_number: ECS-2520MV-250-CN-TR; Mistral Part No: 130020110041-R; Package: SMD; Part_type: OSCILLATORS; Project: AM64X_SKEVM; RoHS: RoHS; Temperature: -40°C+85°C; Tolerance: NA; Voltage: NA; Wattage: NA; Weight: 311mg; Datasheet: Y:\MIS_DATABASE\DATASHEETS\MISC\CRY_OSC\ECS-2520MV.PDF
U55 = SN74CB3Q3257PWR_TSSOP16: IC 4BIT 1-OF-2 FET MULTIPLEXER/DEMULTIPLEXER TSSOP16; Chkd/date: SUHAS/251010; Crtd /date: USMAN/060109; Custom_Duty: 15%; Customs_HS_Code: 85423100; Distributor_name: DIGIKEY; Distributor_part_number: 296-19138-1-ND; Height: 1.20MM; Mfr_name: TEXAS INSTRUMENTS; Mistral Part No: 141009030117-R; Package: TSSOP16; Part_type: ICS\DIGITAL\COMBINATIONAL; Project: OMAP_EVM; RoHS: Sb/ Br FREE; Temperature: -40°C+85°C; Datasheet: Y:\MIS_DATABASE\DATASHEETS\ICS\DIGITAL\COMBINATIONAL\SN74CB3Q3257.PDF
U96 U116 = SN74LVC1G11DCKR_SC70-6: IC SINGLE 3-INPUT POSITIVE-AND GATE SON6; Chkd/date: MANIRAJA/270121; Crtd /date: ALVY/270121; Custom_Duty: 15%; Customs_HS_Code: 85423100; Distributor_name: DIGIKEY; Distributor_part_number: 296-30120-1-ND; Footprint Path: Y:\MIS_DATABASE\Library\ALTIUM_TOOL\PCB_FOOTPRINTS\Altium_Footprint_Lib.PcbLib; Height: 0.60MM; Library Path: Y:\MIS_DATABASE\Library\ALTIUM_TOOL\SCHEMATICS_PARTS\MS_GATE_Library.schlib; Mfr_name: TEXAS INSTRUMENTS; Mistral Part No: 141021010013-R; Package: SON6; Part_type: ICS\DIGITAL\GATES; Project: AM64X_SKEVM; RoHS: RoHS; Temperature: -40°C+125°C; Tolerance: NA; Voltage: NA; Wattage: NA; Weight: 33mg; Datasheet: Y:\MIS_DATABASE\DATASHEETS\ICS\DIGITAL\GATES\SN74LVC1G_NOV16.PDF
D3 D12 D13 = DIODE_SOD323: DIODE 1CH ESD PROTECTION X1SON2; Chkd/date: MANIRAJA/040420; Crtd /date: VASANTHA/181114; Custom_Duty: 15%; Customs_HS_Code: 85423100; Distributor_name: DIGIKEY; Distributor_part_number: 296-30406-1-ND; Footprint Path: Y:\MIS_DATABASE\Library\ALTIUM_TOOL\PCB_FOOTPRINTS\Altium_Footprint_Lib.PcbLib; Height: 0.45MM; Library Path: Y:\MIS_DATABASE\Library\ALTIUM_TOOL\SCHEMATICS_PARTS\MS_DISCRETE_Library.schlib; Mfr_name: TEXAS INSTRUMENTS; Mistral Part No: 130014110022-R; Package: X1SON2; Part_type: DIODE; Project: GALILEO_EVM; RoHS: RoHS; Temperature: -40°C+125°C; Tolerance: NA; Voltage: NA; Wattage: NA; Weight: 1mg; Datasheet: Y:\MIS_DATABASE\DATASHEETS\ICS\INTERFACE\TPD1E10B06-SER.PDF
Q3 Q13 Q14 = MOSFET_IRLML6401TR: TRANSISTOR MOSFET P-CHANNEL SOT23-3; Chkd/date: SHREESHAIL/020206; Crtd /date: MAZHAR/040505; Custom_Duty: 15%; Customs_HS_Code: 85412900; Distributor_name: DIGIKEY; Distributor_part_number: IRLML6401PBFCT-ND; Height: 1.11MM; Mfr_name: IRF; Mfr_part_number: IRLML6401TRPBF; Mistral Part No: 130009031213-P; Package: SOT23-3; Part_type: TRANSISTOR\MOSFET; Project: G4_SVGA; RoHS: Pb-Free; Temperature: -55°C+150°C; Tolerance: NA; Voltage: NA; Wattage: NA; Weight: NA; Datasheet: Y:\MIS_DATABASE\DATASHEETS\DISCRETES\TRANSISTORS_FETS\IRLML6401.PDF
R512 R572 = RESISTOR: RES 4.7K 1/20W 5% 0201; Chkd/date: MANIRAJA/200921; Crtd /date: ALVY/200921; Custom_Duty: 15%; Customs_HS_Code: 85332119; Distributor_name: DIGIKEY; Distributor_part_number: 311-4.7KNCT-ND; Footprint Path: Y:\MIS_DATABASE\Library\ALTIUM_TOOL\PCB_FOOTPRINTS\Altium_Footprint_Lib.PcbLib; Height: 0.26MM; Library Path: Y:\MIS_DATABASE\Library\ALTIUM_TOOL\SCHEMATICS_PARTS\MS_DISCRETE_Library.schlib; Manufacturer: YAGEO AMERICA; Mfr_name: YAGEO AMERICA; Mfr_part_number: RC0201JR-074K7L; Mistral Part No: 110021090007-R; Package: 0201; Part_type: RESISTORS\FIXED; Project: TI_AM62x SKEVM_BRD; RoHS: RoHS; Temperature: -55°C+125°C; Tolerance: 5%; Voltage: NA; Wattage: 1/20W; Weight: 0.17mg; Datasheet: Y:\MIS_DATABASE\DATASHEETS\RESISTORS\RCXXXXL-SER_MAR18.PDF
SW1 SW4 SW5 = 7914G-1-000E__7914G: SWITCH SPST-NO 4MM SQ SMD 7914G; Chkd/date: VASANTHA/271216; Crtd /date: BAVISH/051010; Custom_Duty: 24%; Customs_HS_Code: 85369090; Distributor_name: DIGIKEY; Distributor_part_number: 7914G-000ECT-ND; Height: 4.19MM; Library Ref: 7914G-1-000E _7914G; Mfr_name: BOURNS; Mistral Part No: 130015110004-R; Package: 7914G; Part_type: ELECTRO-MECHANICAL\SWITCH; Project: AAAUC; RoHS: RoHS; Temperature: -55°C+125°C; Tolerance: NA; Voltage: NA; Wattage: NA; Weight: NA; Datasheet: Y:\MIS_DATABASE\DATASHEETS\ICS\DIGITAL\COMBINATIONAL\7914G-1-000E.PDF
U35 U108 = SN74LVC3G17DCUR_VSSOP8: IC TRIPLE SCHMITT-TRIGGER BUFFER VSSOP8; Chkd/date: MANIRAJA/280917; Crtd /date: MANIRAJA/280917; Custom_Duty: 15%; Customs_HS_Code: 85423100; Distributor_name: DIGIKEY; Distributor_part_number: 296-18818-1-ND; Height: 0.90MM; Mfr_name: TEXAS INSTRUMENTS; Mistral Part No: 141017090019-R; Package: VSSOP8; Part_type: ICS\DIGITAL\COMBINATIONAL; Project: TI_MAXIE_CPB; RoHS: RoHS; Temperature: -40°C+125°C; Tolerance: NA; Voltage: NA; Wattage: NA; Weight: 9.6mg; Datasheet: Y:\MIS_DATABASE\DATASHEETS\ICS\DIGITAL\COMBINATIONAL\SN74LVC3G17.PDF
ACC1 = ACCESSORY: ACCESSORIE BGA SOCKET AM62A SVB SoC MICROPROCESSOR FCBGA484; Chkd/date: ALVY/180422; Crtd /date: ALVY/180422; Custom_Duty: NA; Customs_HS_Code: NA; Distributor_name: NA; Distributor_part_number: NA; Footprint Path: NA; Height: 10.69MM; Library Path: NA; Mfr_name: IRONWOOD ELECTRONICS; Mistral Part No: 160022040013; Package: FCBGA484; Part_type: ACCESSORIES; Project: TI_AM62A_SVB_BRD; RoHS: NA; Temperature: NA; Tolerance: NA; Voltage: NA; Wattage: NA; Weight: NA; Datasheet: Y:\MIS_DATABASE\DATASHEETS\MISC\ACCESSORIES\GT-BGA-2001.PDF
ACC2 ACC3 = ACCESSORY: ACCESSORIE JUMPER SHORTING GOLD FLASH; Chkd/date: SUHAS\211010; Crtd /date: USMAN/301208; Distributor_name: DIGIKEY; Distributor_part_number: S9001-ND; Footprint Path: Y:\MIS_DATABASE\Library\ALTIUM_TOOL\PCB_FOOTPRINTS\Altium_Footprint_Lib.PcbLib; Library Path: Y:\MIS_DATABASE\Library\ALTIUM_TOOL\SCHEMATICS_PARTS\MS_MECHANICAL_Library.schlib; Mfr_name: SULLINS CONNECTOR; Mistral Part No: 160009030153-R; Part_type: ACCESSORIES; Project: SMART VIEW_NVR; RoHS: RoHS; Temperature: -55°C+105°C; Datasheet: Y:\MIS_DATABASE\DATASHEETS\MISC\MODULES\SPC02SYAN.PDF
ACC4 = ACCESSORY: STANDOFF BOARD TO BOARD 1.50MM LENGTH FEMALE M2 THREADED SS; Chkd/date: MANIRAJA/280219; Crtd /date: ALVY/280219; Distributor_name: DIGIKEY; Distributor_part_number: 732-7069-1-ND; Mfr_name: WURTH ELECTRONICS; Mistral Part No: 160019020049-R; Package: SS; Part_type: MECHANICAL\STANDOFF; Project: TI_J7ES_EVM_CP; RoHS: RoHS; Weight: 178mg; Datasheet: Y:\MIS_DATABASE\DATASHEETS\MISC\MECHANICAL\9774015243R.PDF
FID1-FID6 = Fiducial
LBL1 LBL2 = ACCESSORY_THT-3-423-10: ACCESSORIE 1 WORKHORSE POLYSTER LABLE 0.25" X 1"; Chkd/date: MANIRAJA/270218; Crtd /date: ALVY/260218; Footprint Path: Y:\MIS_DATABASE\Library\ALTIUM_TOOL\PCB_FOOTPRINTS\Altium_Footprint_Lib.PcbLib; Library Path: Y:\MIS_DATABASE\Library\ALTIUM_TOOL\SCHEMATICS_PARTS\MS_MECHANICAL_Library.schlib; Mfr_name: BRADY; Mistral Part No: 160018020185; Part_type: ACCESSORIES; Project: TI_MAXIE_CPB
LOGO1 LOGO3 LOGO4 = TI_Logo
LOGO2 = FCC_disclaimer
MH3 = WASHER_FLAT: FLAT WASHER FOR M2 NYLON; Chkd/date: MANIRAJA/110319; Crtd /date: ALVY/110319; Distributor_name: DIGIKEY; Distributor_part_number: 36-3356-ND; Mfr_name: KEYSTONE; Mfr_part_number: 3356; Mistral Part No: 160019030017-R; Package: NYLON; Part_type: MECHANICAL\WASHERS; Project: TI_J7ES_EVM_CP; RoHS: RoHS; Datasheet: Y:\MIS_DATABASE\DATASHEETS\MISC\MECHANICAL\3356.PDF
MH5 = SCREW_PAN: PHILLIPS PAN HEAD SCREW - M2 X 5; Chkd/date: MANIRAJA/150319; Crtd /date: MANIRAJA/150319; Distributor_name: DIGIKEY; Distributor_part_number: H738-ND; Height: 5.00MM; Mfr_name: B AND F FASTENER; Mfr_part_number: MPMS 002 0005 PH; Mistral Part No: 160019030026-R; Part_type: MECHANICAL\SCREWS; Project: TI_J7ES_EVM_CP; RoHS: RoHS; Datasheet: Y:\MIS_DATABASE\DATASHEETS\MISC\MECHANICAL\SCREW_MPMSXXX.PDF
PCB1 = PCB_0: AM62A SKEVM; Mfr_part_number: PROC135A; Mistral Part No: FY22-23/00176000401

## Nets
DGND: C12.1 C104.2 C110.1 C134.1 C183.1 C439.1 C462.1 C484.1 C485.1 C487.1 C558.2 C560.2 C577.1 D3.1 D12.1 D13.1 Q3.3(D) Q13.3(D) Q14.3(D) R14.1 R104.2 R184.2 R284.1 R430.2 SW1.1 SW1.4 SW4.1 SW4.4 SW5.1 SW5.4 U6.2(GND) U35.4(GND) U55.8(GND) U96.2(GND) U108.4(GND) U116.2(GND) ; also on sheet 10 11 12 13 14 15 16 17 18 19 20 21 22 23 24 25 26 27 28 29 30 31 32 33 34 35 36 37 38 39 40 41
VCC1V8_CLKBUF: C12.2 C560.1 R23.2 U6.4(VDD) ; also on sheet 25
VCC1V8_SYS: C439.2 R454.1 U96.5(VCC) ; also on sheet 13 18 19 21 34 37 39 40
VCC_3V3_SYS: C183.2 C462.2 C487.2 R13.2 R183.1 R408.1 R409.1 R433.1 R434.1 R505.1 R534.2 R538.1 R539.1 R544.1 U55.16(VCC) U108.8(VCC) U116.5(VCC) ; also on sheet 10 11 13 14 18 19 20 22 23 24 26 27 29 30 31 33 34 35 36 37 38 39 40 41
VCC_5V0_PG: U116.3(B) ; also on sheet 11
CAN_FD_WKUP_SW_INH: U35.7(1Y) ; also on sheet 34
CAN_IO_3V3: C104.1 R149.1 U35.8(VCC) ; also on sheet 13 15 31 34
CLKOUT0: R27.2 R28.2 ; also on sheet 25
CLKOUT_OSC: R27.1 U6.3(OUTPUT)
CONN_MCU_PORz: U96.1(A) ; also on sheet 34
CONN_MCU_RESETz: Q3.1(G) ; also on sheet 34
CPSW_ETH_INTn: R53.1 ; also on sheet 23
CSI_GPIO2: U55.6(2B2) ; also on sheet 37
CSI_GPIO3: U55.3(1B2) ; also on sheet 37
CSI_GPIO4: U55.10(3B2) ; also on sheet 37
DEBOUNCE_CAN_FD_WKUP: C110.2 D3.2 R149.2 SW1.2 SW1.3 U35.1(1A)
DEBOUNCE_GPIO_INT_MCU_SoC: C484.2 D12.2 Q13.2(S) R538.2 SW5.2 SW5.3 U108.3(2A)
Debounce_MCU_RESETz: C134.2 Q3.2(S) R183.2 TP70.1(TP) U108.1(1A)
DEBOUNCE_SOC_WARMRESETn: C485.2 D13.2 Q14.2(S) R539.2 SW4.2 SW4.3 U108.6(3A)
EXP_CLKOUT0: R59.1 ; also on sheet 33
EXP_GPIO1_22: U18.F14(UART0_CTSN) ; also on sheet 33
EXP_SPI0_CLK: U55.2(1B1) ; also on sheet 33
EXP_SPI0_CS0: U55.11(3B1) ; also on sheet 33
EXP_SPI0_CS1: U18.C16(SPI0_CS1) ; also on sheet 33
EXP_SPI0_D0: U55.5(2B1) ; also on sheet 33
EXP_SPI0_D1: U18.E15(SPI0_D1) ; also on sheet 33
EXP_UART5_RXD: U18.B17(MCAN0_TX) ; also on sheet 33
EXP_UART5_TXD: U18.C18(MCAN0_RX) ; also on sheet 33
EXT_CLKOUT0: R28.1 R60.1
EXT_CLKOUT0_R: R59.2 R60.2 U18.B16(EXT_REFCLK1)
EXTINTn_RC: C577.2 R654.1 U18.F17(EXTINTN)
GPIO1_23_INTn: R512.2 U18.C15(UART0_RTSN) ; also on sheet 40
GPIO_MCU_SoC: R512.1 R572.1 U108.5(2Y)
GPIO_MCU_SoC_INTn: R572.2 ; also on sheet 34
JTAG_EMU_RSTn: U116.6(C) ; also on sheet 30
MCU_PORz: C558.1 R184.1 R454.2 TP69.1(TP) U18.A7(MCU_PORZ) U96.4(Y)
MCU_RESETSTATz: U18.D14(MCU_RESETSTATZ) ; also on sheet 34
MCU_RESETz: R505.2 TP80.1(TP) U18.C12(MCU_RESETZ) U108.7(1Y)
MCU_SAFETY_ERRORz_1V8: U18.B8(MCU_ERRORN) ; also on sheet 34
PMIC_INTn: R53.2 R654.2 ; also on sheet 13
PMIC_POWERGOOD: U116.1(A) ; also on sheet 13
PORz_OUT: R104.1 TP63.1(TP) U18.F18(PORZ_OUT) ; also on sheet 20 23 24 27
RESETSTATz: R430.1 TP65.1(TP) U18.F19(RESETSTATZ) ; also on sheet 19 20 21 23 24 27 38 39 40 41
SoC_I2C0_SCL: R408.2 R757.2 ; also on sheet 10 13 22 33
SoC_I2C0_SDA: R409.2 R758.2 ; also on sheet 10 13 22 33
SOC_I2C1_SCL: R433.2 R759.2 ; also on sheet 14 22 26 39 40 41
SOC_I2C1_SDA: R434.2 R760.2 ; also on sheet 14 22 26 39 40 41
SoC_PORz: R544.2 U96.3(B) U116.4(Y)
SoC_SPI0_CLK: R761.2 U55.4(1A)
SoC_SPI0_CS0: U18.D16(SPI0_CS0) U55.9(3A)
SoC_SPI0_D0: U18.B15(SPI0_D0) U55.7(2A)
SOC_UART0_RX_3V3: U18.E14(UART0_RXD) ; also on sheet 31
SOC_UART0_TX_3V3: U18.D15(UART0_TXD) ; also on sheet 31
SoC_WARM_RESETZ: R534.1 TP87.1(TP) U18.E19(RESET_REQZ) U108.2(3Y)
SPI0_FET_OE: R284.2 U55.15(~{OE}) ; also on sheet 40
SPI0_FET_SEL: R13.1 R14.2 U55.1(S) ; also on sheet 40
TEST_GPIO1: Q13.1(G) ; also on sheet 26 28
TEST_PORZn: U96.6(C) ; also on sheet 26 28
TEST_WARMRESETn: Q14.1(G) ; also on sheet 26 28
N16947096: R23.1 U6.1(TRI-STATE)
N23178675: TP96.1(TP) U55.14(4B1)
N23178691: TP94.1(TP) U55.13(4B2)
N23178707: TP93.1(TP) U55.12(4A)
N24621303: R757.1 U18.D17(I2C0_SCL)
N24621306: R758.1 U18.E16(I2C0_SDA)
N24621309: R759.1 U18.C17(I2C1_SCL)
N24621312: R760.1 U18.E17(I2C1_SDA)
N24621315: R761.1 U18.A17(SPI0_CLK)

Not connected (* = marked no-connect by the designer): U18 C6(RSVD0)* D6(RSVD1)* E7(RSVD2)*; U35 2(3Y)* 3(2A)* 5(2Y)* 6(3A)*

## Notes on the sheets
sheet 42
- D-Note:
  I2C0_, I2C1_
  Emulated Open Drain output type
  I2C interface. A 47R series resistor
  is added to control the fall time
  Note the exceptions related to
  emulated open drain output type
  I2C interface in the processor-specific
  data sheet
- D-Note:
  Open-drain output type buffer
  I2C interfaces have slew rate
  requirement specified when
  pulled to 3.3 V. An RC can be
  used to limit the slew rate
- OSCILLATOR
- D-Note :-
  The TXD and RXD net names for UART
  are reverse with respect to
  MCAN(Refer pin attributes section of
  the data sheet)
  Take note while connecting
- SOC - GENERAL
- D-Note:
  Add 10K pulldown
  when EXT_CLKOUT0
  is configured as
  peripheral clock
- GPIO1_24
- GPIO1_26
- GPIO1_25
- GPIO1_27
- C
- GPIO_22
- GPIO1_28
- GPIO1_29
- GPIO_23
- GPIO1_17
- C
- [SCLK/GPO]
- GPIO1_18
- [MOSI/GPIO]
- GPIO1_19
- V
- D-Note:
  RESERVED PINS
  Leave them unconnected
- GPIO1_15
- [CS/GPIO]
- GPIO1_16
- D-Note:
  RESERVED PINS
  Leave
  unconnected
- D-Note:
  SoC IO buffers are off during reset. A
  parallel pull is recommended near
  to the attached device input that is being
  driven by the SoC IO (input does not
  float).
- D-Note:
  Recommended
  oscillator
  part number
  LMK6CE02500DDLFT
- ECS-2520MV-250-CN-TR
- D-Note:
  EXT_REFCLK1 configured as CLKOUT0:
  A clock signal should always be
  connected point-to-point. When
  connecting CLKOUT to more than
  one (multiple)  attached devices
  clock input, consider using a
  clock fanout buffer such as
  LMK1C110n (n = 2:4 or more,
  buffer with one input
  and multiple outputs)
- D-Note:
  Refer to the processor-specific data sheet for
  oscillator specifications when the external
  oscillator is used along with clock buffer and
  also when the oscillator is directly connected
  as processor clock input.
- SoC SPI0 FET SWITCH
- DNI
- 25Mhz XTAL
- MCU_OSC0_XI
- EXT_REFCLK1
- DNI
- CLK
- CLK
- [SCLK/GPO]
- MOSI
- MOSI
- [MOSI/GPIO]
- ETH1
- 1:4 CLK BUFF
- CS
- CS
- ETH2
- [CS/GPIO]
- CSI
- 25Mhz Osc
- INPUT/OUTPUT
- OEn
- SEL
- An
- L
- L(DEFAULT)
- An=nB1
- EXP HDR
- D-Note:
  Provide provision for a pull-down.
  Populate when an attached device
  is connected. Refer to the SoC
  datasheet for Pin Connectivity
  Requirements.
- L
- H
- An=nB2
- MIPI CSI
- SOC - RESETS - COLD AND WARM
- D-Note:
  EXTINTn is an open-drain output
  type buffer, fail-safe IO. An external
  pull-up is recommended when a trace or
  external input is connected.
- D-Note:
  Pull-down resistor on PORz_OUT and RESETSTATz is provided
  to hold the attached device in reset condition during
  SoC reset and power-up.
- MCU POWER ON RESET
- D-Note:
  Not connecting a valid MCU_PORz input could
  cause unpredictable and probably random
  behavior. Since the processor is not getting a
  valid reset, internal circuits would be in random
  states. Slow rising reset signal could cause
  glitches internal to the processor reset circuit.
  The recommendation is to connect the output
  from the logic gate or a discrete buffer
  (with fast rise time) as input to MCU_PORz,
  rather than a slow rising open-drain output
  (from PMIC of similar sources).
- D-Note:
  Open-drain output type IO EXTINTn has slew rate limit specified,
  when pulled to a 3.3 V supply. An RC is added to limit the slew rate
- C
- D-Note:
  MCU_PORz input has slew rate
  requirements specified. Lesser the
  slew, the better when PMIC_POWERGOOD
  is connected as MCU_PORz input. Adjust
  the PMIC_POWERGOOD pull-up to
  minimize the slew (100-200
  ns) when using an open drain
  output. MCU_PORz is fail-safe and
  3.3 V tolerant. Therefore, you can
  pull the MCU_PORz signal to either
  1.8 V or 3.3 V.
- D-Note:
  22pF glitch filter
  has been added
  to improve EMC
  robustness
- R-Note :-
  MCU_PORz has
  pulldown
  configured
- C
sheet 43
- SOC RESETS - COLD AND WARM
- DEBOUNCE CIRCUIT
- SOC MCU WARM RESET
- D-Note :-
  DNI Q3 and C134
  Refer to Errata
  i2407— RESET: MCU_RESETSTATz
  unreliable when MCU_RESETz is
  asserted low
- D-Note:
  LVCMOS inputs have slew rate requirements specified. A
  Schmitt trigger based debouncing logic is used for the slow
  ramp warm reset inputs. Debounce circuit is recommended  when
  push button or RC is used.
- SOC WARM RESET
- Silk: RST
- USER INTERRUPT
- Silk: INT
sheet 44
- CAN-FD FAST WAKE UP SW
- Silk: RST
- D-Note :-
  Terminate the unused
  inputs as per the
  device data sheet
  recommendations
sheet 45
- MOUNTING HARDWARE
- LOGOs
- ASSEMBLY NOTES
- BARE PCB
- 1. All MSL components should be baked as per JEDEC standard.
  2. PCB should be baked at 120 degree for 8 hours.
  3. Board assembly must comply with workmanship standards.
  IPC-A-610 Class 2, unless otherwise specified.
  4. These assemblies are ESD sensitive, ESD precautions
  shall be observed.
  5. These assemblies must be clean and free from flux and
  all contaminants. Use of no clean flux is not acceptable.
  6. Provide serial numbers to the assembled boards for identification.
  7. The assembled board are wrapped in ESD Covers(individual) and
  packed securely before shipment.
- Texas Intruments
- For Evaluation only; not FCC approved for resale
- WEEE Mark
- CE Mark
- JUMPERS
- AM62A SOCKET
- FIDUCIALS
- LABELS
- SCREW & WASHER FOR PCIe M.2
- Board Serial No.
- Assembly Revision
- D-Note :-
  Refer STRAP CONFIGURATION OF
  ETHERNET PHYS page from
  SK-AM64B schematics
